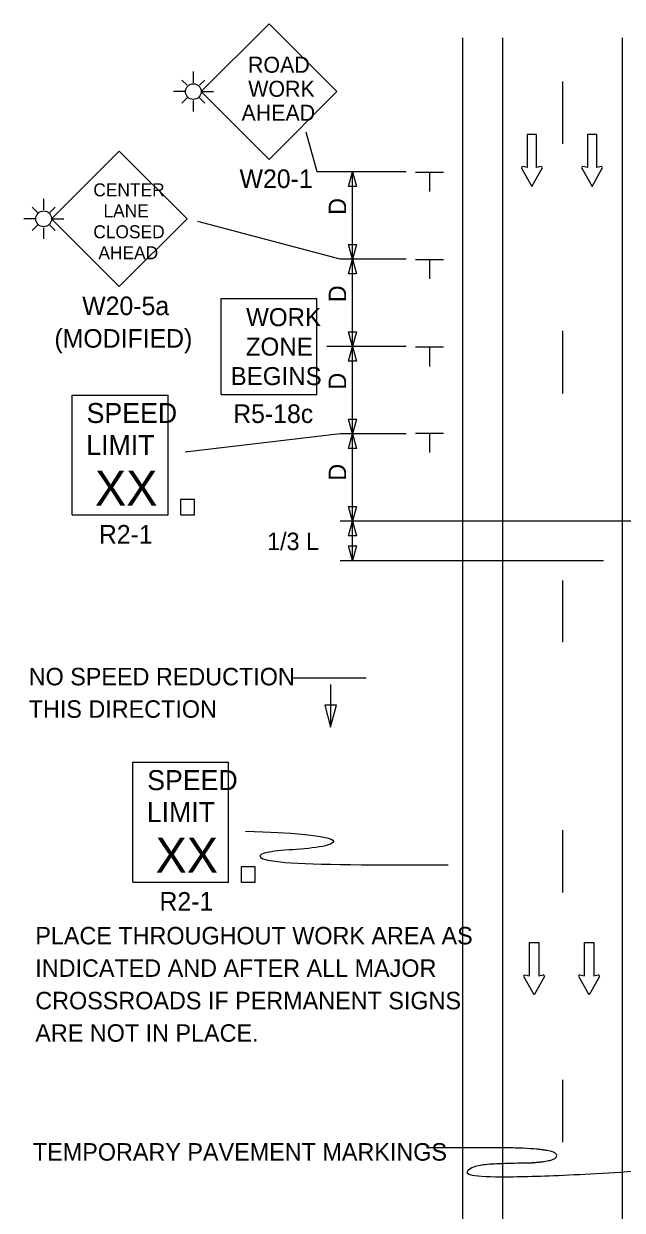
# Model space of a CAD drawing. Extents: x 16577 to 18475, y 5712 to 6909.
# Drawn here: x 16730.9 to 16970.7, y 6431.6 to 6907 of the extents above; entities that cross this region are included whole.
import ezdxf

# ---------------------------------------------------------------- set-up
doc = ezdxf.new("R2010")
doc.units = 0
for name, color, linetype in [('ALI_LEGAL_EX', 7, 'Continuous'), ('Level 3', 7, 'Continuous'), ('MT_SCRATCH_LEVEL_E', 7, 'Continuous'), ('PAVT_EDGE_EX', 7, 'Continuous'), ('TRAFFIC_SIGNS_PR', 7, 'Continuous'), ('TYPICAL_TEXT_DIMEN_PR', 7, 'Continuous')]:
    doc.layers.add(name, color=color, linetype=linetype)

msp = doc.modelspace()

# ---------------------------------------------------------------- linework, layer by layer
at = {"layer": 'ALI_LEGAL_EX'}
for points in [[(16946.75, 6883.94), (16946.75, 6858.94)], [(16946.75, 6783.94), (16946.75, 6758.94)], [(16946.75, 6683.94), (16946.75, 6659.28)], [(16946.75, 6583.94), (16946.75, 6558.94)], [(16946.75, 6483.94), (16946.75, 6458.94)]]:
    msp.add_lwpolyline(points, dxfattribs=at)
at = {"layer": 'Level 3'}
for p, q in [((16884.13, 6847.73), (16848.44, 6847.73)), ((16884.13, 6812.73), (16857.65, 6812.73)), ((16884.13, 6777.73), (16852.33, 6777.73)), ((16884.13, 6742.73), (16857.65, 6742.73))]:
    msp.add_line(p, q, dxfattribs=at)
at = {"layer": 'MT_SCRATCH_LEVEL_E'}
for p, q in [((16936.42, 6862.73), (16932.68, 6862.73)), ((16932.68, 6862.73), (16932.68, 6849.48)), ((16936.42, 6862.73), (16932.68, 6862.73)), ((16932.68, 6862.73), (16932.68, 6849.48)), ((16936.42, 6849.48), (16936.42, 6862.73)), ((16936.42, 6849.48), (16936.42, 6862.73)), ((16960.49, 6862.73), (16956.75, 6862.73)), ((16956.75, 6862.73), (16956.75, 6849.48)), ((16960.49, 6862.73), (16956.75, 6862.73)), ((16956.75, 6862.73), (16956.75, 6849.48)), ((16960.49, 6849.48), (16960.49, 6862.73)), ((16960.49, 6849.48), (16960.49, 6862.73)), ((16930.42, 6849.11), (16934.57, 6841.87)), ((16930.42, 6849.11), (16934.57, 6841.87)), ((16932.68, 6849.48), (16930.9, 6849.79)), ((16932.68, 6849.48), (16930.9, 6849.79)), ((16934.57, 6841.87), (16938.68, 6849.11)), ((16934.57, 6841.87), (16938.68, 6849.11)), ((16938.2, 6849.79), (16936.42, 6849.48)), ((16938.2, 6849.79), (16936.42, 6849.48)), ((16954.49, 6849.11), (16958.64, 6841.87)), ((16954.49, 6849.11), (16958.64, 6841.87)), ((16956.75, 6849.48), (16954.97, 6849.79)), ((16956.75, 6849.48), (16954.97, 6849.79)), ((16958.64, 6841.87), (16962.75, 6849.11)), ((16958.64, 6841.87), (16962.75, 6849.11)), ((16962.27, 6849.79), (16960.49, 6849.48)), ((16962.27, 6849.79), (16960.49, 6849.48)), ((16933.54, 6525.61), (16933.54, 6538.86)), ((16933.54, 6538.86), (16937.28, 6538.86)), ((16933.54, 6525.61), (16933.54, 6538.86)), ((16933.54, 6538.86), (16937.28, 6538.86)), ((16937.28, 6538.86), (16937.28, 6525.61)), ((16937.28, 6538.86), (16937.28, 6525.61)), ((16955.57, 6525.61), (16955.57, 6538.86)), ((16955.57, 6538.86), (16959.31, 6538.86)), ((16955.57, 6525.61), (16955.57, 6538.86)), ((16955.57, 6538.86), (16959.31, 6538.86)), ((16959.31, 6538.86), (16959.31, 6525.61)), ((16959.31, 6538.86), (16959.31, 6525.61)), ((16935.39, 6517.99), (16931.28, 6525.24)), ((16935.39, 6517.99), (16931.28, 6525.24)), ((16931.76, 6525.92), (16933.54, 6525.61)), ((16931.76, 6525.92), (16933.54, 6525.61)), ((16939.54, 6525.24), (16935.39, 6517.99)), ((16939.54, 6525.24), (16935.39, 6517.99)), ((16937.28, 6525.61), (16939.06, 6525.92)), ((16937.28, 6525.61), (16939.06, 6525.92)), ((16957.42, 6517.99), (16953.31, 6525.24)), ((16957.42, 6517.99), (16953.31, 6525.24)), ((16953.8, 6525.92), (16955.57, 6525.61)), ((16953.8, 6525.92), (16955.57, 6525.61)), ((16961.57, 6525.24), (16957.42, 6517.99)), ((16961.57, 6525.24), (16957.42, 6517.99)), ((16959.31, 6525.61), (16961.09, 6525.92)), ((16959.31, 6525.61), (16961.09, 6525.92))]:
    msp.add_line(p, q, dxfattribs=at)
for centre, start, end in [((16930.83, 6849.33), 80.0362, 209.7731), ((16930.83, 6849.33), 80.0362, 209.7731), ((16938.27, 6849.33), 330.4248, 99.9638), ((16938.27, 6849.33), 330.4248, 99.9638), ((16954.9, 6849.33), 80.0362, 209.7731), ((16954.9, 6849.33), 80.0362, 209.7731), ((16962.34, 6849.33), 330.4248, 99.9638), ((16962.34, 6849.33), 330.4248, 99.9638), ((16931.69, 6525.46), 80.0362, 209.5752), ((16931.69, 6525.46), 80.0362, 209.5752), ((16939.13, 6525.46), 330.2269, 99.9638), ((16939.13, 6525.46), 330.2269, 99.9638), ((16953.72, 6525.46), 80.0362, 209.5752), ((16953.72, 6525.46), 80.0362, 209.5752), ((16961.16, 6525.46), 330.2269, 99.9638), ((16961.16, 6525.46), 330.2269, 99.9638)]:
    msp.add_arc(centre, 0.463, start, end, dxfattribs=at)
at = {"layer": 'PAVT_EDGE_EX'}
for p, q in [((16906.75, 6901.43), (16906.75, 6139.45)), ((16922.75, 6901.43), (16922.75, 6139.45)), ((16970.75, 6901.43), (16970.75, 6139.45))]:
    msp.add_line(p, q, dxfattribs=at)
at = {"layer": 'TRAFFIC_SIGNS_PR'}
for p, q in [((16829.22, 6907.05), (16802.04, 6879.86)), ((16856.41, 6879.86), (16829.22, 6907.05)), ((16796.37, 6882.37), (16794.26, 6884.48)), ((16798.89, 6883.42), (16798.89, 6887.92)), ((16801.4, 6882.37), (16803.51, 6884.48)), ((16795.73, 6879.86), (16790.89, 6879.86)), ((16802.04, 6879.86), (16829.22, 6852.67)), ((16802.04, 6879.86), (16806.92, 6879.86)), ((16829.22, 6852.67), (16856.41, 6879.86)), ((16796.37, 6877.35), (16794.26, 6875.24)), ((16798.89, 6871.89), (16798.89, 6876.31)), ((16801.4, 6877.35), (16803.51, 6875.24)), ((16769.2, 6856.04), (16742.05, 6828.88)), ((16796.35, 6828.88), (16769.2, 6856.04)), ((16738.9, 6832.44), (16738.9, 6836.94)), ((16736.38, 6831.4), (16734.27, 6833.51)), ((16741.41, 6831.4), (16743.52, 6833.51)), ((16735.74, 6828.88), (16730.9, 6828.88)), ((16742.05, 6828.88), (16746.93, 6828.88)), ((16742.05, 6828.88), (16769.2, 6801.73)), ((16769.2, 6801.73), (16796.35, 6828.88)), ((16736.38, 6826.37), (16734.27, 6824.26)), ((16738.9, 6820.92), (16738.9, 6825.33)), ((16741.41, 6826.37), (16743.52, 6824.26)), ((16810.02, 6758.52), (16810.02, 6796.92)), ((16810.02, 6796.92), (16848.42, 6796.92)), ((16848.42, 6758.52), (16848.42, 6796.92)), ((16750.34, 6758.21), (16788.74, 6758.21)), ((16750.34, 6710.21), (16750.34, 6758.21)), ((16788.74, 6710.21), (16788.74, 6758.21)), ((16810.02, 6758.52), (16848.42, 6758.52)), ((16750.34, 6710.21), (16788.74, 6710.21)), ((16774.62, 6611.12), (16813.02, 6611.12)), ((16774.62, 6563.12), (16774.62, 6611.12)), ((16813.02, 6563.12), (16813.02, 6611.12)), ((16774.62, 6563.12), (16813.02, 6563.12))]:
    msp.add_line(p, q, dxfattribs=at)
for points in [[(16793.76, 6710.21), (16799.35, 6710.21), (16799.35, 6716.38), (16793.76, 6716.38)], [(16818.04, 6563.12), (16823.63, 6563.12), (16823.63, 6569.29), (16818.04, 6569.29)]]:
    msp.add_lwpolyline(points, close=True, dxfattribs=at)
for centre in [(16798.88, 6879.86), (16738.89, 6828.88)]:
    msp.add_circle(centre, 3.15, dxfattribs=at)
at = {"layer": 'TYPICAL_TEXT_DIMEN_PR'}
for p, q in [((16848.44, 6847.73), (16844.07, 6863.64)), ((16861.08, 6841.87), (16862.65, 6847.73)), ((16862.65, 6847.73), (16864.22, 6841.87)), ((16862.65, 6812.73), (16862.65, 6847.73)), ((16887.9, 6847.56), (16899.15, 6847.56)), ((16893.53, 6847.56), (16893.53, 6839.77)), ((16862.65, 6841.87), (16861.08, 6841.87)), ((16864.22, 6841.87), (16862.65, 6841.87)), ((16857.65, 6812.73), (16800.7, 6827.85)), ((16862.65, 6812.73), (16861.08, 6818.6)), ((16861.08, 6818.6), (16862.65, 6818.6)), ((16862.65, 6818.6), (16864.22, 6818.6)), ((16864.22, 6818.6), (16862.65, 6812.73)), ((16861.08, 6806.87), (16862.65, 6812.73)), ((16862.65, 6812.73), (16864.22, 6806.87)), ((16862.65, 6777.73), (16862.65, 6812.73)), ((16887.9, 6812.56), (16899.15, 6812.56)), ((16893.53, 6812.56), (16893.53, 6804.77)), ((16862.65, 6806.87), (16861.08, 6806.87)), ((16864.22, 6806.87), (16862.65, 6806.87)), ((16862.65, 6777.73), (16861.08, 6783.6)), ((16861.08, 6783.6), (16862.65, 6783.6)), ((16862.65, 6783.6), (16864.22, 6783.6)), ((16864.22, 6783.6), (16862.65, 6777.73)), ((16861.08, 6771.87), (16862.65, 6777.73)), ((16862.65, 6777.73), (16864.22, 6771.87)), ((16862.65, 6742.73), (16862.65, 6777.73)), ((16887.9, 6777.56), (16899.15, 6777.56)), ((16893.53, 6777.56), (16893.53, 6769.77)), ((16862.65, 6771.87), (16861.08, 6771.87)), ((16864.22, 6771.87), (16862.65, 6771.87)), ((16862.65, 6742.73), (16861.08, 6748.6)), ((16861.08, 6748.6), (16862.65, 6748.6)), ((16862.65, 6748.6), (16864.22, 6748.6)), ((16864.22, 6748.6), (16862.65, 6742.73)), ((16857.65, 6742.73), (16795.55, 6735.45)), ((16861.08, 6736.87), (16862.65, 6742.73)), ((16862.65, 6707.73), (16862.65, 6742.73)), ((16862.65, 6742.73), (16864.22, 6736.87)), ((16887.9, 6743.02), (16899.15, 6743.02)), ((16893.53, 6743.02), (16893.53, 6735.24)), ((16862.65, 6736.87), (16861.08, 6736.87)), ((16864.22, 6736.87), (16862.65, 6736.87)), ((16862.65, 6707.73), (16861.08, 6713.6)), ((16861.08, 6713.6), (16862.65, 6713.6)), ((16862.65, 6713.6), (16864.22, 6713.6)), ((16864.22, 6713.6), (16862.65, 6707.73)), ((16987.84, 6707.73), (16857.65, 6707.73)), ((16861.08, 6701.87), (16862.65, 6707.73)), ((16862.65, 6691.97), (16862.65, 6707.73)), ((16862.65, 6707.73), (16864.22, 6701.87)), ((16862.65, 6701.87), (16861.08, 6701.87)), ((16864.22, 6701.87), (16862.65, 6701.87)), ((16862.65, 6691.97), (16861.08, 6697.83)), ((16861.08, 6697.83), (16862.65, 6697.83)), ((16862.65, 6697.83), (16864.22, 6697.83)), ((16864.22, 6697.83), (16862.65, 6691.97)), ((16857.65, 6691.98), (16963.28, 6691.98)), ((16868.06, 6644.84), (16838.62, 6644.84)), ((16853.88, 6642.34), (16853.88, 6625.21)), ((16853.88, 6634.01), (16851.53, 6634.01)), ((16851.53, 6634.01), (16853.88, 6625.21)), ((16853.88, 6625.21), (16856.24, 6634.01)), ((16856.24, 6634.01), (16853.88, 6634.01))]:
    msp.add_line(p, q, dxfattribs=at)
for points, degree in [([(16819.79, 6583.51), (16859.2, 6582.37), (16856.82, 6576.16), (16823.54, 6576.16), (16823.54, 6570), (16871.84, 6570), (16900.97, 6570)], 3), ([(16991.03, 6448.11), (16908.56, 6442.63), (16908.56, 6450.51), (16944.52, 6450.51), (16944.52, 6456.66), (16896.23, 6456.66), (16892.29, 6456.66)], 2)]:
    msp.add_open_spline(points, degree=degree, dxfattribs=at)

# ---------------------------------------------------------------- texts
at = {"layer": 'TRAFFIC_SIGNS_PR'}
for s, height, p in [('ROAD', 6.408, (16820.76, 6887.41)), ('WORK', 6.408, (16820.86, 6877.79)), ('AHEAD', 6.408, (16818.17, 6868.18)), ('W20-1', 7.449, (16817.38, 6841.22)), ('CENTER', 5.2, (16758.78, 6837.89)), ('LANE', 5.2, (16762.85, 6829.49)), ('CLOSED', 5.2, (16758.78, 6821.09)), ('AHEAD', 5.2, (16760.81, 6812.69)), ('W20-5a', 7.44, (16754.34, 6790.29)), ('WORK', 7.217, (16820.02, 6785.88)), ('(MODIFIED)', 7.44, (16743.2, 6777.25)), ('ZONE', 7.217, (16819.91, 6774.07)), ('BEGINS', 7.217, (16813.83, 6762.26)), ('SPEED', 8, (16756.11, 6747.07)), ('R5-18c', 7.44, (16814.84, 6747.08)), ('LIMIT', 8, (16755.95, 6734.27)), ('XX', 14.031, (16759.46, 6713.97)), ('R2-1', 7.44, (16761.02, 6698.77)), ('SPEED', 8, (16780.39, 6599.98)), ('LIMIT', 8, (16780.23, 6587.18)), ('XX', 14.031, (16783.73, 6566.88)), ('R2-1', 7.44, (16785.3, 6551.68)), ('PLACE THROUGHOUT WORK AREA AS', 7, (16735.54, 6538.16)), ('INDICATED AND AFTER ALL MAJOR', 7, (16735.54, 6525.16)), ('CROSSROADS IF PERMANENT SIGNS', 7, (16735.54, 6512.16)), ('ARE NOT IN PLACE.', 7, (16735.54, 6499.16))]:
    msp.add_text(s, height=height, dxfattribs=at).set_placement(p)
at = {"layer": 'TYPICAL_TEXT_DIMEN_PR'}
for p in [(16860.09, 6830.45), (16860.09, 6795.45), (16860.09, 6760.45), (16860.09, 6723.96)]:
    msp.add_text('D', height=7, rotation=90, dxfattribs=at).set_placement(p)
for s, p in [('1/3 L', (16828.41, 6696.15)), ('NO SPEED REDUCTION', (16732.9, 6641.96)), ('THIS DIRECTION', (16732.9, 6628.96)), ('TEMPORARY PAVEMENT MARKINGS', (16734.6, 6451.52))]:
    msp.add_text(s, height=7, dxfattribs=at).set_placement(p)

doc.saveas('drawing.dxf')
